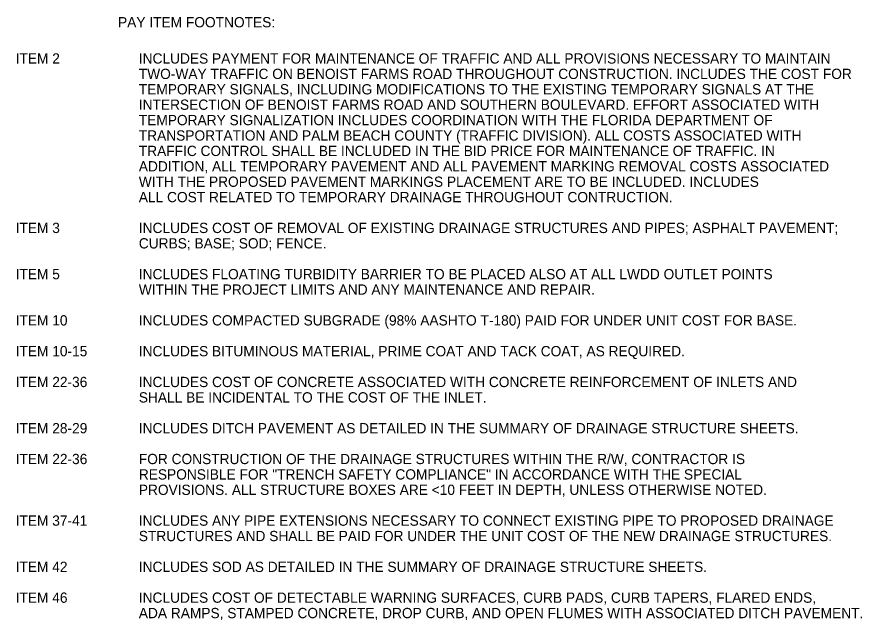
# Model space of a CAD drawing. Extents: x 0.3 to 14.6, y -0.2 to 9.6.
# Drawn here: x 8.89 to 14.65, y 5.18 to 9.29 of the extents above; entities that cross this region are included whole.
import ezdxf

# ---------------------------------------------------------------- set-up
doc = ezdxf.new("R2010")
doc.units = 0
doc.layers.add('TextNotes', color=7, linetype='Continuous')

msp = doc.modelspace()

# ---------------------------------------------------------------- texts
at = {"layer": 'TextNotes'}
for s, p in [('PAY ITEM FOOTNOTES:', (9.5752, 9.2175)), ('ITEM 2', (8.8769, 8.9704)), ('INCLUDES PAYMENT FOR MAINTENANCE OF TRAFFIC AND ALL PROVISIONS NECESSARY TO MAINTAIN ', (9.7169, 8.9704)), ('TWO-WAY TRAFFIC ON BENOIST FARMS ROAD THROUGHOUT CONSTRUCTION. INCLUDES THE COST FOR ', (9.7169, 8.8654)), ('TEMPORARY SIGNALS, INCLUDING MODIFICATIONS TO THE EXISTING TEMPORARY SIGNALS AT THE ', (9.7169, 8.7604)), ('INTERSECTION OF BENOIST FARMS ROAD AND SOUTHERN BOULEVARD. EFFORT ASSOCIATED WITH ', (9.7169, 8.6554)), ('TEMPORARY SIGNALIZATION INCLUDES COORDINATION WITH THE FLORIDA DEPARTMENT OF ', (9.7169, 8.5504)), ('TRANSPORTATION AND PALM BEACH COUNTY (TRAFFIC DIVISION). ALL COSTS ASSOCIATED WITH ', (9.7169, 8.4454)), ('TRAFFIC CONTROL SHALL BE INCLUDED IN THE BID PRICE FOR MAINTENANCE OF TRAFFIC. IN ', (9.7169, 8.3404)), ('ADDITION, ALL TEMPORARY PAVEMENT AND ALL PAVEMENT MARKING REMOVAL COSTS ASSOCIATED ', (9.7169, 8.2354)), ('WITH THE PROPOSED PAVEMENT MARKINGS PLACEMENT ARE TO BE INCLUDED. INCLUDES', (9.7169, 8.1304)), ('ALL COST RELATED TO TEMPORARY DRAINAGE THROUGHOUT CONTRUCTION.', (9.7169, 8.0254)), ('ITEM 3', (8.8769, 7.8154)), ('INCLUDES COST OF REMOVAL OF EXISTING DRAINAGE STRUCTURES AND PIPES; ASPHALT PAVEMENT; ', (9.7169, 7.8154)), ('CURBS; BASE; SOD; FENCE.', (9.7169, 7.7104)), ('ITEM 5', (8.8769, 7.5004)), ('INCLUDES FLOATING TURBIDITY BARRIER TO BE PLACED ALSO AT ALL LWDD OUTLET POINTS', (9.7169, 7.5004)), ('WITHIN THE PROJECT LIMITS AND ANY MAINTENANCE AND REPAIR.', (9.7169, 7.3954)), ('ITEM 10', (8.8769, 7.1854)), ('INCLUDES COMPACTED SUBGRADE (98% AASHTO T-180) PAID FOR UNDER UNIT COST FOR BASE.', (9.7169, 7.1854)), ('ITEM 10-15   ', (8.8769, 6.9754)), ('INCLUDES BITUMINOUS MATERIAL, PRIME COAT AND TACK COAT, AS REQUIRED.', (9.7169, 6.9754)), ('ITEM 22-36', (8.8769, 6.7654)), ('INCLUDES COST OF CONCRETE ASSOCIATED WITH CONCRETE REINFORCEMENT OF INLETS AND', (9.7169, 6.7654)), ('SHALL BE INCIDENTAL TO THE COST OF THE INLET.', (9.7169, 6.6604)), ('ITEM 28-29', (8.8769, 6.4504)), ('INCLUDES DITCH PAVEMENT AS DETAILED IN THE SUMMARY OF DRAINAGE STRUCTURE SHEETS.', (9.7169, 6.4504)), ('ITEM 22-36', (8.8769, 6.2404)), ('FOR CONSTRUCTION OF THE DRAINAGE STRUCTURES WITHIN THE R/W, CONTRACTOR IS ', (9.7169, 6.2404)), ('RESPONSIBLE FOR "TRENCH SAFETY COMPLIANCE" IN ACCORDANCE WITH THE SPECIAL', (9.7169, 6.1354)), ('PROVISIONS. ALL STRUCTURE BOXES ARE <10 FEET IN DEPTH, UNLESS OTHERWISE NOTED.', (9.7169, 6.0304)), ('ITEM 37-41', (8.8769, 5.8204)), ('INCLUDES ANY PIPE EXTENSIONS NECESSARY TO CONNECT EXISTING PIPE TO PROPOSED DRAINAGE', (9.7169, 5.8204)), ('STRUCTURES AND SHALL BE PAID FOR UNDER THE UNIT COST OF THE NEW DRAINAGE STRUCTURES.', (9.7169, 5.7154)), ('ITEM 42', (8.8769, 5.5054)), ('INCLUDES SOD AS DETAILED IN THE SUMMARY OF DRAINAGE STRUCTURE SHEETS.', (9.7169, 5.5054)), ('ITEM 46', (8.8769, 5.2954)), ('INCLUDES COST OF DETECTABLE WARNING SURFACES, CURB PADS, CURB TAPERS, FLARED ENDS, ', (9.7169, 5.2954)), ('ADA RAMPS, STAMPED CONCRETE, DROP CURB, AND OPEN FLUMES WITH ASSOCIATED DITCH PAVEMENT.', (9.7169, 5.1904))]:
    msp.add_text(s, height=0.07, dxfattribs=at).set_placement(p)

doc.saveas('drawing.dxf')
